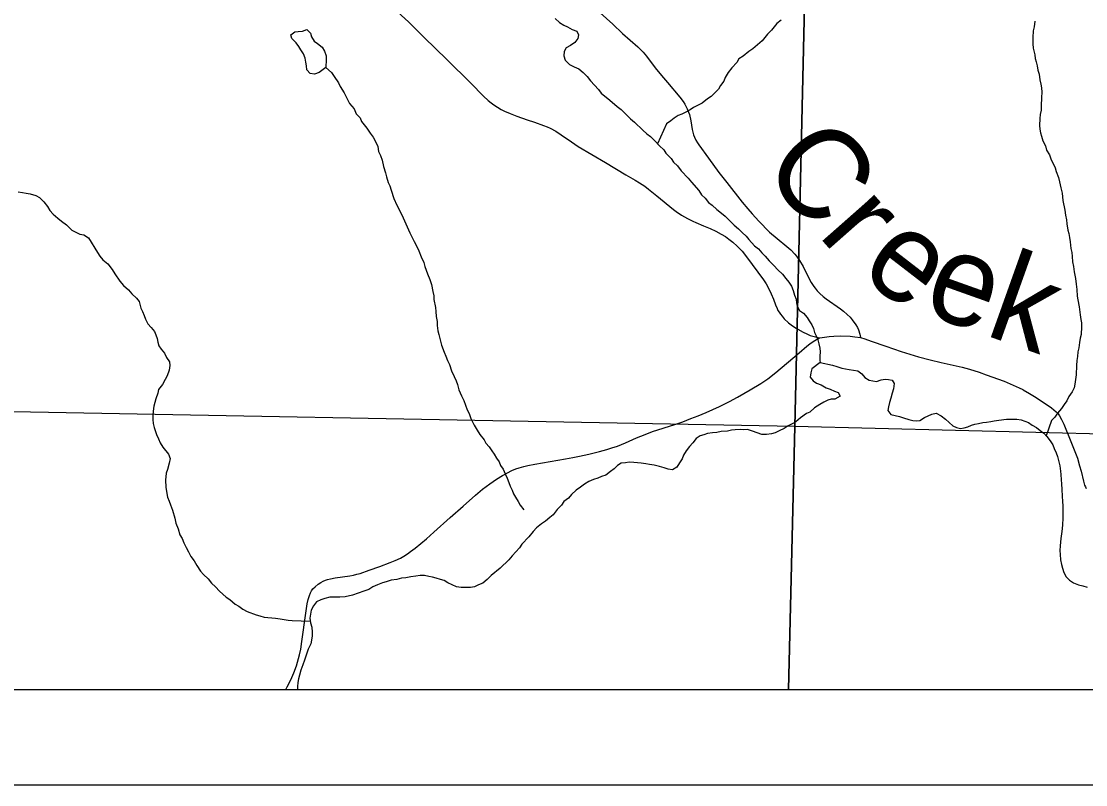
# Model space of a CAD drawing. Extents: x -7.9 to 76.1, y 0 to 22.
# Drawn here: x 3.501 to 4.618, y 14 to 14.801 of the extents above; entities that cross this region are included whole.
import ezdxf

# ---------------------------------------------------------------- set-up
doc = ezdxf.new("R2010")
doc.units = 0
for name, color, linetype in [('GM_X_County_Road', 7, 'Continuous'), ('GM_X_Minor_River', 7, 'Continuous'), ('GM_X_Minor_River_Text', 7, 'Continuous'), ('GM_X_Section', 7, 'Continuous'), ('GM_X_Township_Road', 7, 'Continuous'), ('SC_Scratch1', 7, 'Continuous'), ('SH_Data', 7, 'Continuous')]:
    doc.layers.add(name, color=color, linetype=linetype)

msp = doc.modelspace()

# ---------------------------------------------------------------- linework, layer by layer
at = {"layer": 'GM_X_County_Road'}
msp.add_lwpolyline([(3.8886, 14.8178), (3.9076, 14.8005), (3.924, 14.7843), (3.9478, 14.7612), (3.9731, 14.7363), (3.9863, 14.7228), (3.9912, 14.7182), (3.9945, 14.7157), (3.9972, 14.7135), (4.001, 14.711), (4.0047, 14.7088), (4.0083, 14.7069), (4.0142, 14.7044), (4.0212, 14.7017), (4.0322, 14.6979), (4.04, 14.6953), (4.0493, 14.692), (4.0533, 14.6904), (4.0563, 14.6889), (4.0622, 14.6858), (4.0678, 14.6822), (4.0787, 14.6746), (4.0858, 14.6699), (4.1145, 14.6529), (4.1356, 14.6402), (4.1454, 14.6346), (4.1499, 14.6318), (4.1555, 14.6281), (4.1595, 14.6252), (4.1683, 14.6182), (4.1857, 14.6038), (4.1887, 14.6016), (4.1942, 14.5979), (4.2005, 14.5942), (4.2062, 14.5914), (4.2093, 14.59), (4.2174, 14.5866), (4.2242, 14.5838), (4.2303, 14.5808), (4.2359, 14.5779), (4.2404, 14.5753), (4.244, 14.5726), (4.248, 14.5694), (4.2527, 14.5651), (4.2578, 14.56), (4.2624, 14.5541), (4.2743, 14.5379), (4.2801, 14.5297), (4.2829, 14.5256), (4.2858, 14.5204), (4.2883, 14.5151), (4.2906, 14.5097), (4.2929, 14.5038), (4.2945, 14.4998), (4.2954, 14.4977), (4.2965, 14.4959), (4.2979, 14.4938), (4.2997, 14.4916), (4.302, 14.4891), (4.3065, 14.4848), (4.3093, 14.4826), (4.3128, 14.4802), (4.3161, 14.4782), (4.322, 14.4749), (4.3258, 14.4731), (4.3293, 14.4716), (4.3333, 14.4703), (4.3361, 14.4696), (4.3392, 14.4691), (4.3492, 14.4703), (4.3541, 14.4708), (4.3612, 14.4711), (4.3711, 14.4706), (4.376, 14.4702), (4.382, 14.4692), (4.3867, 14.468), (4.3934, 14.4655), (4.4085, 14.4601), (4.4248, 14.4547), (4.443, 14.4491), (4.4553, 14.446), (4.4668, 14.443), (4.4888, 14.4382), (4.4966, 14.436), (4.5067, 14.4328), (4.5141, 14.4302), (4.5327, 14.4234), (4.5393, 14.4208), (4.5487, 14.4166), (4.5524, 14.4147), (4.5527, 14.4145), (4.5596, 14.4107), (4.5648, 14.4075), (4.578, 14.3988), (4.5825, 14.3956), (4.5876, 14.3914), (4.5896, 14.3891), (4.5911, 14.3871), (4.5932, 14.3834), (4.5954, 14.3785), (4.6036, 14.3583), (4.6097, 14.3428), (4.6121, 14.3347), (4.6136, 14.3289), (4.616, 14.3186), (4.6173, 14.3144), (4.6181, 14.3125), (4.619, 14.3108)], dxfattribs=at)
at = {"layer": 'GM_X_Minor_River'}
for points in [[(4.0615, 14.8043), (4.0661, 14.7998), (4.0707, 14.7972), (4.0745, 14.7954), (4.0795, 14.7925), (4.0844, 14.7907), (4.086, 14.7869), (4.0853, 14.7831), (4.0823, 14.7789), (4.0775, 14.7758), (4.073, 14.7734), (4.0708, 14.7696), (4.0705, 14.765), (4.0721, 14.7605), (4.0767, 14.756), (4.0816, 14.7535), (4.0862, 14.7513), (4.0908, 14.7476), (4.0951, 14.7431), (4.0986, 14.7386), (4.107, 14.7296), (4.1097, 14.7259), (4.119, 14.7185), (4.1266, 14.7118), (4.1309, 14.7085), (4.1355, 14.704), (4.1405, 14.6988), (4.1447, 14.6954), (4.1536, 14.6869), (4.1578, 14.6832), (4.1616, 14.6802), (4.1662, 14.6757), (4.1709, 14.6705)], [(4.2988, 14.8024), (4.2943, 14.7989), (4.2887, 14.792), (4.2843, 14.7877), (4.2787, 14.7808), (4.269, 14.7723), (4.2649, 14.7696), (4.2589, 14.7645), (4.2544, 14.7618), (4.2522, 14.758), (4.247, 14.7522), (4.2433, 14.7476), (4.24, 14.7422), (4.2386, 14.7384), (4.2352, 14.7338), (4.233, 14.73), (4.2289, 14.7257), (4.2252, 14.7222), (4.2215, 14.7199), (4.2159, 14.7153), (4.2069, 14.7106), (4.2031, 14.7082), (4.1986, 14.7059), (4.1945, 14.7039), (4.1908, 14.7023), (4.1866, 14.6996), (4.1829, 14.6969), (4.1784, 14.6937), (4.169, 14.6726)], [(4.5652, 14.8014), (4.5645, 14.7953), (4.5634, 14.7911), (4.5628, 14.7843), (4.5629, 14.7775), (4.5634, 14.7729), (4.565, 14.7661), (4.5655, 14.7623), (4.5663, 14.7586), (4.5675, 14.7544), (4.5683, 14.7499), (4.5695, 14.7457), (4.5704, 14.7397), (4.5712, 14.7351), (4.5721, 14.7314), (4.5725, 14.7268), (4.5722, 14.7211), (4.5716, 14.7124), (4.5717, 14.7079), (4.5706, 14.7033), (4.5703, 14.6991), (4.5701, 14.6919), (4.5702, 14.6881), (4.571, 14.6843), (4.5722, 14.6806), (4.5734, 14.6757), (4.5761, 14.6704), (4.5774, 14.6659), (4.5805, 14.661), (4.5821, 14.6557), (4.5844, 14.652), (4.5864, 14.6475), (4.5876, 14.6437), (4.59, 14.6373), (4.5908, 14.6328), (4.5924, 14.6263), (4.5936, 14.6207), (4.5945, 14.6131), (4.5966, 14.6029), (4.5971, 14.5976), (4.5983, 14.5927), (4.5987, 14.5886), (4.5996, 14.5821), (4.6008, 14.5784), (4.6016, 14.5742), (4.6021, 14.5697), (4.603, 14.5629), (4.6038, 14.5587), (4.6043, 14.5542), (4.6047, 14.5489), (4.6056, 14.5439), (4.6064, 14.5383), (4.6077, 14.5311), (4.6085, 14.5254), (4.609, 14.5197), (4.6095, 14.5126), (4.6103, 14.5088), (4.6116, 14.5016), (4.6125, 14.4933), (4.6133, 14.4884), (4.6142, 14.4846), (4.6142, 14.4804), (4.6136, 14.4724), (4.6126, 14.4686), (4.6119, 14.4641), (4.6112, 14.4584), (4.6102, 14.4542), (4.6099, 14.4493), (4.6092, 14.4451), (4.6089, 14.4401), (4.6083, 14.4303), (4.607, 14.4204), (4.6063, 14.4166), (4.6044, 14.4124), (4.6007, 14.4074), (4.5986, 14.4028), (4.596, 14.399), (4.593, 14.3948), (4.5889, 14.3898), (4.586, 14.3859), (4.5826, 14.3821), (4.577, 14.3661)], [(3.8207, 14.7526), (3.8138, 14.7476), (3.809, 14.7456), (3.8044, 14.7463), (3.8009, 14.7504), (3.8005, 14.7546), (3.7997, 14.7584), (3.7992, 14.7625), (3.7972, 14.767), (3.7945, 14.7712), (3.7926, 14.7749), (3.7895, 14.7787), (3.7852, 14.7831), (3.784, 14.7869), (3.7881, 14.79), (3.7919, 14.7904), (3.7964, 14.7909), (3.801, 14.7925), (3.8048, 14.7888), (3.8056, 14.785), (3.8084, 14.7805), (3.8122, 14.7779), (3.8168, 14.7742), (3.8195, 14.7697), (3.8211, 14.7648), (3.8212, 14.761), (3.8207, 14.7526)], [(3.8207, 14.7528), (3.8267, 14.7475), (3.8294, 14.7433), (3.8341, 14.7366), (3.836, 14.7328), (3.8399, 14.7261), (3.8423, 14.722), (3.8458, 14.7148), (3.8505, 14.7092), (3.8528, 14.704), (3.8567, 14.6999), (3.8582, 14.6961), (3.8637, 14.689), (3.8672, 14.6837), (3.8706, 14.6796), (3.873, 14.6751), (3.8754, 14.6699), (3.8762, 14.6646), (3.8782, 14.6604), (3.8798, 14.6555), (3.8814, 14.6487), (3.8834, 14.6423), (3.8846, 14.6378), (3.8862, 14.6321), (3.8878, 14.6284), (3.8894, 14.6239), (3.8922, 14.6152), (3.8953, 14.6084), (3.8989, 14.6017), (3.902, 14.5949), (3.9048, 14.5885), (3.9091, 14.5791), (3.9134, 14.5701), (3.9157, 14.5663), (3.9185, 14.5603), (3.9209, 14.5539), (3.9236, 14.5479), (3.9248, 14.5437), (3.9276, 14.5362), (3.93, 14.5302), (3.9316, 14.5249), (3.9332, 14.5177), (3.9341, 14.5132), (3.9341, 14.5094), (3.9358, 14.5007), (3.9363, 14.4966), (3.9367, 14.4913), (3.9376, 14.486), (3.9376, 14.4818), (3.9385, 14.4765), (3.9393, 14.4724), (3.941, 14.4656), (3.9422, 14.4614), (3.9449, 14.4539), (3.9469, 14.4497), (3.9485, 14.4452), (3.9505, 14.4411), (3.9528, 14.4343), (3.9556, 14.4283), (3.9576, 14.4238), (3.9591, 14.42), (3.9604, 14.4143), (3.9631, 14.4083), (3.9655, 14.4034), (3.9675, 14.3985), (3.9691, 14.3933), (3.9714, 14.3895), (3.973, 14.3842), (3.9765, 14.3775), (3.9797, 14.3722), (3.9824, 14.3677), (3.987, 14.3621), (3.9886, 14.3584), (3.9924, 14.3546), (3.9952, 14.3505), (3.9975, 14.3468), (3.9998, 14.3426), (4.0026, 14.3389), (4.0041, 14.3351), (4.0069, 14.331), (4.0092, 14.3261), (4.0112, 14.3216), (4.0128, 14.3171), (4.0144, 14.3133), (4.0163, 14.3092), (4.0179, 14.3054), (4.0199, 14.3017), (4.0226, 14.2972), (4.0249, 14.2934), (4.0288, 14.2886)], [(4.1709, 14.6705), (4.1755, 14.6664), (4.1778, 14.6627), (4.1832, 14.6571), (4.1859, 14.6533), (4.1898, 14.6496), (4.1937, 14.6444), (4.201, 14.6365), (4.2045, 14.6324), (4.2122, 14.6235), (4.2153, 14.619), (4.2191, 14.6156), (4.2226, 14.6111), (4.2264, 14.6082), (4.2314, 14.6037), (4.236, 14.6), (4.2399, 14.5967), (4.2495, 14.5873), (4.2541, 14.5833), (4.258, 14.5795), (4.2622, 14.5758), (4.2649, 14.5721), (4.2707, 14.5657), (4.2749, 14.5624), (4.2784, 14.5583), (4.2819, 14.5546), (4.2861, 14.5497), (4.2911, 14.5449), (4.2954, 14.5404), (4.3, 14.5359), (4.3038, 14.5314), (4.3069, 14.5273), (4.3096, 14.5232), (4.3112, 14.5187), (4.3128, 14.5138), (4.3144, 14.5096), (4.3149, 14.5059), (4.3157, 14.5021), (4.318, 14.4976), (4.3222, 14.495), (4.3261, 14.4905), (4.3281, 14.4868), (4.3308, 14.4826), (4.3327, 14.4789), (4.3339, 14.4747), (4.3355, 14.471), (4.3371, 14.4668), (4.3383, 14.4627), (4.3392, 14.4581), (4.3396, 14.4544), (4.3393, 14.4498), (4.3394, 14.4453), (4.3398, 14.443)], [(3.4978, 14.6223), (3.5023, 14.6216), (3.5061, 14.6209), (3.5103, 14.6202), (3.5164, 14.6184), (3.5202, 14.6162), (3.5248, 14.6118), (3.5287, 14.6069), (3.531, 14.6028), (3.5345, 14.5987), (3.5395, 14.5946), (3.5433, 14.5916), (3.5487, 14.5875), (3.5541, 14.582), (3.5625, 14.5779), (3.5667, 14.5772), (3.5717, 14.5739), (3.581, 14.5585), (3.5837, 14.5548), (3.5868, 14.5507), (3.5918, 14.5466), (3.5964, 14.5406), (3.5992, 14.5361), (3.6046, 14.5286), (3.6085, 14.5238), (3.6138, 14.5193), (3.6173, 14.5152), (3.6219, 14.5107), (3.6247, 14.507), (3.6267, 14.5002), (3.6282, 14.4965), (3.6302, 14.4923), (3.6314, 14.4885), (3.6341, 14.4837), (3.6376, 14.4799), (3.6411, 14.4758), (3.6423, 14.4721), (3.6439, 14.4683), (3.6443, 14.4645), (3.6455, 14.4607), (3.6478, 14.457), (3.6513, 14.4529), (3.6537, 14.4484), (3.6568, 14.4439), (3.6572, 14.4401), (3.6562, 14.4352), (3.6544, 14.4291), (3.6522, 14.4252), (3.6492, 14.4199), (3.6452, 14.4149), (3.6445, 14.4111), (3.6423, 14.405)], [(4.3398, 14.443), (4.3308, 14.4364), (4.3298, 14.4322), (4.3291, 14.4276), (4.3322, 14.4239), (4.336, 14.4213), (4.3406, 14.4195), (4.3459, 14.4166), (4.3501, 14.4151), (4.3547, 14.4129), (4.3585, 14.4115), (4.3608, 14.4077), (4.3552, 14.4046), (4.3514, 14.4045), (4.3477, 14.4037), (4.3435, 14.4014), (4.3394, 14.399), (4.3338, 14.3955), (4.329, 14.3909), (4.3252, 14.3897), (4.3192, 14.385), (4.314, 14.3808), (4.3103, 14.3788), (4.3061, 14.3768), (4.302, 14.3737), (4.2968, 14.3714), (4.2926, 14.3694), (4.2885, 14.3682), (4.2832, 14.3677), (4.2783, 14.3676), (4.2737, 14.3694), (4.2688, 14.3712), (4.2634, 14.3727), (4.2597, 14.3726), (4.2559, 14.3729), (4.2506, 14.3724), (4.2468, 14.372), (4.2423, 14.3712), (4.2359, 14.3707), (4.2313, 14.3698), (4.2268, 14.3694), (4.2215, 14.3685), (4.2177, 14.3673), (4.2136, 14.3661), (4.2095, 14.3634), (4.2062, 14.3588), (4.2025, 14.3549), (4.1991, 14.3503), (4.1962, 14.3457), (4.1947, 14.3419), (4.1922, 14.3377), (4.1892, 14.3331), (4.1847, 14.3303), (4.1802, 14.331), (4.176, 14.3325), (4.171, 14.3339), (4.1653, 14.3353), (4.1604, 14.336), (4.1566, 14.3367), (4.1517, 14.3373), (4.1479, 14.3377), (4.1441, 14.338), (4.1392, 14.3386), (4.1354, 14.3378), (4.1309, 14.3374), (4.1271, 14.335), (4.1234, 14.3315), (4.1197, 14.3288), (4.1148, 14.3249), (4.1103, 14.3234), (4.1062, 14.3218), (4.1016, 14.3202), (4.0968, 14.3182), (4.0923, 14.3155), (4.0882, 14.3124), (4.0837, 14.3092), (4.0788, 14.3046), (4.0755, 14.3008), (4.0706, 14.2973), (4.0681, 14.2934), (4.0636, 14.2888), (4.0595, 14.2834), (4.0558, 14.2803), (4.0513, 14.2765), (4.0472, 14.2737), (4.042, 14.2695), (4.0386, 14.2656), (4.0338, 14.2602), (4.0264, 14.2525), (4.0242, 14.2487), (4.0201, 14.2444), (4.0164, 14.2402), (4.013, 14.236), (4.0037, 14.2271), (3.9944, 14.2194), (3.9903, 14.2155), (3.9855, 14.2116), (3.981, 14.2096), (3.9768, 14.2077), (3.9727, 14.2068), (3.9678, 14.2068)], [(4.3398, 14.443), (4.3527, 14.4402), (4.3573, 14.4388), (4.3626, 14.4373), (4.3664, 14.4366), (4.3702, 14.4356), (4.3793, 14.4342), (4.3835, 14.4313), (4.3866, 14.4275), (4.3912, 14.4246), (4.3988, 14.4232), (4.4037, 14.4248), (4.4078, 14.4256), (4.4116, 14.4253), (4.4154, 14.4246), (4.4174, 14.4209), (4.4167, 14.4155), (4.4153, 14.411), (4.4139, 14.4056), (4.4124, 14.4011), (4.4114, 14.3965), (4.4107, 14.3927), (4.4138, 14.3886), (4.4229, 14.3865), (4.4271, 14.385), (4.4328, 14.3832), (4.437, 14.3822), (4.4408, 14.3818), (4.4445, 14.3823), (4.4494, 14.3854), (4.4532, 14.387), (4.4569, 14.389), (4.4614, 14.3898), (4.4668, 14.3872), (4.4714, 14.3835), (4.4791, 14.3768), (4.4829, 14.375), (4.4871, 14.3739), (4.4908, 14.3744), (4.4946, 14.3756), (4.4984, 14.3772), (4.5021, 14.3784), (4.5059, 14.3792), (4.5104, 14.38), (4.5142, 14.3805), (4.5187, 14.3813), (4.5225, 14.3818), (4.5274, 14.3826), (4.5353, 14.3835), (4.5463, 14.3837), (4.5508, 14.383), (4.5585, 14.3801), (4.5623, 14.3775), (4.5669, 14.375), (4.5707, 14.3716), (4.5745, 14.369), (4.5776, 14.3653), (4.5811, 14.3608), (4.5838, 14.3567), (4.5854, 14.3529), (4.5874, 14.3484), (4.589, 14.3443), (4.5914, 14.3345), (4.5919, 14.3292), (4.5923, 14.3254), (4.5928, 14.3201), (4.5929, 14.3159), (4.5934, 14.3099), (4.5939, 14.303), (4.594, 14.2974), (4.5944, 14.2928), (4.5946, 14.2833), (4.5943, 14.2795), (4.594, 14.2731), (4.5937, 14.2685), (4.593, 14.2632), (4.5924, 14.2583), (4.5917, 14.2507), (4.5914, 14.2458), (4.5915, 14.2416), (4.592, 14.2359), (4.5932, 14.231), (4.594, 14.2272), (4.5956, 14.2227), (4.598, 14.2182), (4.6014, 14.2145), (4.6057, 14.2119), (4.611, 14.2097), (4.6155, 14.2087), (4.6201, 14.2072)], [(3.6423, 14.405), (3.6402, 14.3973), (3.6395, 14.392), (3.6392, 14.3875), (3.6393, 14.3833), (3.6397, 14.3791), (3.6406, 14.375), (3.643, 14.3675), (3.6453, 14.3629), (3.6469, 14.3588), (3.6496, 14.3543), (3.6558, 14.3468), (3.6574, 14.3423), (3.6564, 14.3374), (3.6546, 14.3309), (3.6531, 14.3271), (3.6525, 14.3195), (3.653, 14.3123), (3.6535, 14.3077), (3.6547, 14.3017), (3.6563, 14.2976), (3.6579, 14.2938), (3.6599, 14.2881), (3.6623, 14.2798), (3.6635, 14.2746), (3.6659, 14.2685), (3.6675, 14.2621), (3.6698, 14.2584), (3.6718, 14.2539), (3.6742, 14.249), (3.6765, 14.2445), (3.6792, 14.2396), (3.6827, 14.2351), (3.6855, 14.2302), (3.6893, 14.2242), (3.6924, 14.2205), (3.6974, 14.216), (3.7009, 14.2115), (3.7048, 14.2078), (3.709, 14.203), (3.7163, 14.197), (3.7201, 14.1944), (3.7255, 14.1896), (3.7293, 14.1874), (3.7335, 14.1844), (3.7381, 14.1819), (3.7477, 14.1782), (3.7515, 14.1772), (3.756, 14.1757), (3.7678, 14.1748), (3.7727, 14.1741), (3.7772, 14.1735), (3.7814, 14.1728), (3.7856, 14.1725), (3.8044, 14.1715)], [(3.9678, 14.2068), (3.9628, 14.207), (3.9579, 14.2077), (3.9488, 14.2117), (3.9449, 14.2143), (3.9411, 14.2154), (3.9366, 14.2168), (3.9328, 14.2179), (3.929, 14.2186), (3.9244, 14.2196), (3.9199, 14.2196), (3.9153, 14.2187), (3.91, 14.2182), (3.9048, 14.217), (3.9002, 14.2166), (3.8953, 14.2153), (3.8893, 14.2145), (3.884, 14.2129), (3.8803, 14.2117), (3.875, 14.2097), (3.8701, 14.2077), (3.866, 14.205), (3.8607, 14.203), (3.8487, 14.199), (3.8412, 14.1973), (3.8355, 14.1968), (3.8249, 14.1967), (3.8196, 14.1954), (3.8155, 14.1942), (3.811, 14.1919), (3.8077, 14.1876), (3.8055, 14.1831), (3.8041, 14.1747), (3.8046, 14.1698), (3.8062, 14.1652), (3.8066, 14.16), (3.8063, 14.1558), (3.8049, 14.1478), (3.8024, 14.1424), (3.7984, 14.1306), (3.7966, 14.1257), (3.7944, 14.1203), (3.793, 14.115), (3.792, 14.1112), (3.7913, 14.1074), (3.791, 14.1032), (3.791, 14.1)]]:
    msp.add_lwpolyline(points, dxfattribs=at)
at = {"layer": 'GM_X_Section'}
for points in [[(4.3363, 15.3822), (4.313, 14.3761), (3.3054, 14.3948), (3.3274, 15.4069)], [(4.3363, 15.3822), (5.3554, 15.3537), (5.3532, 15.2703), (5.3252, 14.3506), (4.313, 14.3761)]]:
    msp.add_lwpolyline(points, close=True, dxfattribs=at)
at = {"layer": 'GM_X_Township_Road'}
for points in [[(4.1088, 14.8101), (4.1219, 14.7981), (4.1323, 14.7885), (4.1482, 14.7745), (4.1538, 14.7688), (4.1573, 14.7647), (4.1665, 14.7525), (4.173, 14.7444), (4.1793, 14.7369), (4.1923, 14.7215), (4.1958, 14.7169), (4.1976, 14.7141), (4.1988, 14.7121), (4.2002, 14.7093), (4.2016, 14.7059), (4.2024, 14.7035), (4.2039, 14.6967), (4.2054, 14.6875), (4.2069, 14.6821), (4.2079, 14.6796), (4.2093, 14.6764), (4.2109, 14.6735), (4.2123, 14.6715), (4.2226, 14.6575), (4.2335, 14.6426), (4.2417, 14.6319), (4.2579, 14.6114), (4.2639, 14.6043), (4.2684, 14.5991), (4.2754, 14.5915), (4.2866, 14.58), (4.2944, 14.5731), (4.3048, 14.565), (4.309, 14.5614), (4.3132, 14.5568), (4.3149, 14.5547), (4.3181, 14.5501), (4.3217, 14.544), (4.3266, 14.5336), (4.3303, 14.527), (4.3331, 14.5227), (4.3344, 14.521), (4.3365, 14.5184), (4.3392, 14.5157), (4.3427, 14.5125), (4.346, 14.5099), (4.361, 14.4996), (4.3642, 14.4971), (4.3682, 14.4936), (4.3711, 14.4906), (4.3733, 14.4879), (4.3772, 14.4826), (4.379, 14.4798), (4.38, 14.4774), (4.3812, 14.473), (4.382, 14.4692)], [(3.7788, 14.1), (3.7803, 14.1027), (3.784, 14.1099), (3.7872, 14.1173), (3.7899, 14.1246), (3.7912, 14.1287), (3.7933, 14.1363), (3.7945, 14.1422), (3.7957, 14.1503), (3.7997, 14.1802), (3.8013, 14.1897), (3.8024, 14.1943), (3.8035, 14.1984), (3.8046, 14.2012), (3.8057, 14.2034), (3.8071, 14.2054), (3.8095, 14.2078), (3.8127, 14.2104), (3.8154, 14.2121), (3.8179, 14.2135), (3.8204, 14.2146), (3.8227, 14.2154), (3.8258, 14.2162), (3.8306, 14.217), (3.8459, 14.2192), (3.8499, 14.22), (3.8533, 14.2208), (3.857, 14.2218), (3.8664, 14.2251), (3.8773, 14.229), (3.8884, 14.2332), (3.8935, 14.2354), (3.8991, 14.2379), (3.9025, 14.2399), (3.9064, 14.2424), (3.9096, 14.2446), (3.9147, 14.2484), (3.9266, 14.2582), (3.934, 14.2649), (3.9512, 14.2803), (3.9649, 14.2924), (3.9779, 14.304), (3.9853, 14.3101), (3.993, 14.3159), (3.9999, 14.3206), (4.0061, 14.3244), (4.0116, 14.3273), (4.0162, 14.3296), (4.0204, 14.3315), (4.0239, 14.3326), (4.0288, 14.3339), (4.0328, 14.3349), (4.0401, 14.3363), (4.0725, 14.3421), (4.0801, 14.3435), (4.0871, 14.3448), (4.097, 14.3469), (4.1082, 14.3497), (4.1156, 14.3517), (4.1211, 14.3534), (4.1269, 14.3554), (4.1353, 14.3587), (4.1469, 14.3639), (4.1561, 14.3677), (4.1636, 14.3706), (4.1872, 14.3782), (4.1955, 14.381), (4.204, 14.3843), (4.2118, 14.3873), (4.2199, 14.3906), (4.2342, 14.397), (4.2444, 14.4021), (4.2528, 14.4067), (4.2664, 14.4144), (4.2774, 14.4211), (4.2846, 14.4261), (4.293, 14.4325), (4.3178, 14.4534), (4.3257, 14.4602), (4.3287, 14.4626), (4.3324, 14.4651), (4.3357, 14.4671), (4.3392, 14.4691)]]:
    msp.add_lwpolyline(points, dxfattribs=at)
at = {"layer": 'SC_Scratch1'}
for points in [[(3.2996, 14.1), (4.3065, 14.1), (4.313, 14.3761), (3.3054, 14.3948)], [(4.3065, 14.1), (5.3191, 14.1), (5.3234, 14.2437), (5.3252, 14.3506), (4.313, 14.3761)]]:
    msp.add_lwpolyline(points, close=True, dxfattribs=at)
at = {"layer": 'SH_Data'}
for p, q in [((2.1, 14.1), (8.9, 14.1)), ((2, 14), (9, 14))]:
    msp.add_line(p, q, dxfattribs=at)

# ---------------------------------------------------------------- texts
at = {"layer": 'GM_X_Minor_River_Text'}
for s, height, rotation, p in [('Cr', 0.09468, 311.3973, (4.2758, 14.646)), ('e', 0.0947, 322.3969, (4.3786, 14.5366)), ('ek', 0.09469, 340.3939, (4.4445, 14.4962))]:
    msp.add_text(s, height=height, rotation=rotation, dxfattribs=at).set_placement(p)

doc.saveas('drawing.dxf')
